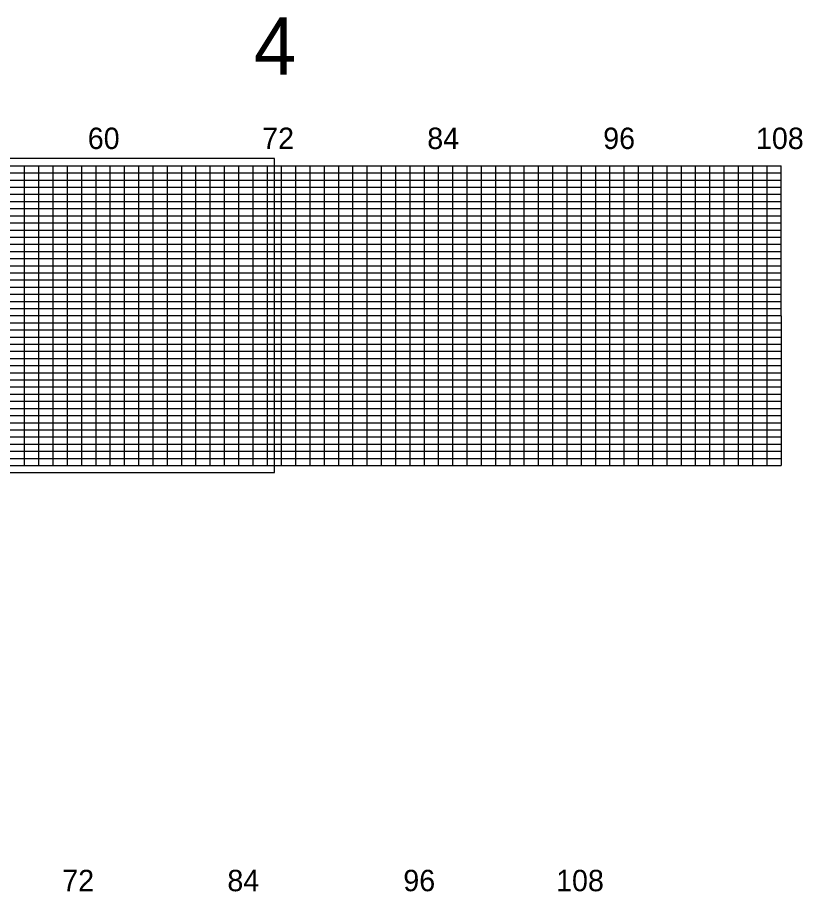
# Model space of a CAD drawing. Extents: x 1894907 to 1905782, y 740939 to 777025.
# Drawn here: x 1898307 to 1901056, y 769322 to 772384 of the extents above; entities that cross this region are included whole.
import ezdxf

# ---------------------------------------------------------------- set-up
doc = ezdxf.new("R2010")
doc.units = 0
for name, color, linetype in [('RD_PD_WallFill', 7, 'Continuous'), ('RD_SHT_IplotShp', 7, 'Continuous'), ('RD_Sketch8', 7, 'Continuous')]:
    doc.layers.add(name, color=color, linetype=linetype)

msp = doc.modelspace()

# ---------------------------------------------------------------- linework, layer by layer
at = {"layer": 'RD_PD_WallFill'}
for p, q in [((1895631.6, 771864.2), (1900981.6, 771864.2)), ((1898331.6, 770814.2), (1898331.6, 771864.2)), ((1898381.6, 770814.2), (1898381.6, 771864.2)), ((1898431.6, 770814.2), (1898431.6, 771864.2)), ((1898481.6, 770814.2), (1898481.6, 771864.2)), ((1898531.6, 770814.2), (1898531.6, 771864.2)), ((1898581.6, 770814.2), (1898581.6, 771864.2)), ((1898631.6, 770814.2), (1898631.6, 771864.2)), ((1898681.6, 770814.2), (1898681.6, 771864.2)), ((1898731.6, 770814.2), (1898731.6, 771864.2)), ((1898781.6, 770814.2), (1898781.6, 771864.2)), ((1898831.6, 770814.2), (1898831.6, 771864.2)), ((1898881.6, 770814.2), (1898881.6, 771864.2)), ((1898931.6, 770814.2), (1898931.6, 771864.2)), ((1898981.6, 770814.2), (1898981.6, 771864.2)), ((1899031.6, 770814.2), (1899031.6, 771864.2)), ((1899081.6, 770814.2), (1899081.6, 771864.2)), ((1899131.6, 770814.2), (1899131.6, 771864.2)), ((1899181.6, 770814.2), (1899181.6, 771864.2)), ((1899231.6, 770814.2), (1899231.6, 771864.2)), ((1899281.6, 770814.2), (1899281.6, 771864.2)), ((1899331.6, 770814.2), (1899331.6, 771864.2)), ((1899381.6, 770814.2), (1899381.6, 771864.2)), ((1899431.6, 770814.2), (1899431.6, 771864.2)), ((1899481.6, 770814.2), (1899481.6, 771864.2)), ((1899531.6, 770814.2), (1899531.6, 771864.2)), ((1899581.6, 770814.2), (1899581.6, 771864.2)), ((1899631.6, 770814.2), (1899631.6, 771864.2)), ((1899681.6, 770814.2), (1899681.6, 771864.2)), ((1899731.6, 770814.2), (1899731.6, 771864.2)), ((1899781.6, 770814.2), (1899781.6, 771864.2)), ((1899831.6, 770814.2), (1899831.6, 771864.2)), ((1899881.6, 770814.2), (1899881.6, 771864.2)), ((1899931.6, 770814.2), (1899931.6, 771864.2)), ((1899981.6, 770814.2), (1899981.6, 771864.2)), ((1900031.6, 770814.2), (1900031.6, 771864.2)), ((1900081.6, 770814.2), (1900081.6, 771864.2)), ((1900131.6, 770814.2), (1900131.6, 771864.2)), ((1900181.6, 770814.2), (1900181.6, 771864.2)), ((1900231.6, 770814.2), (1900231.6, 771864.2)), ((1900281.6, 770814.2), (1900281.6, 771864.2)), ((1900331.6, 770814.2), (1900331.6, 771864.2)), ((1900381.6, 770814.2), (1900381.6, 771864.2)), ((1900431.6, 770814.2), (1900431.6, 771864.2)), ((1900481.6, 770814.2), (1900481.6, 771864.2)), ((1900531.6, 770814.2), (1900531.6, 771864.2)), ((1900581.6, 770814.2), (1900581.6, 771864.2)), ((1900631.6, 770814.2), (1900631.6, 771864.2)), ((1900681.6, 770814.2), (1900681.6, 771864.2)), ((1900731.6, 770814.2), (1900731.6, 771864.2)), ((1900781.7, 770814.2), (1900781.6, 771864.2)), ((1900831.6, 770814.2), (1900831.7, 771864.2)), ((1900881.6, 770814.2), (1900881.6, 771864.2)), ((1900931.6, 770814.2), (1900931.6, 771864.2)), ((1900981.7, 770814.2), (1900981.6, 771864.2)), ((1896081.6, 771839.2), (1900981.6, 771839.2)), ((1896081.6, 771814.2), (1900981.6, 771814.2)), ((1896081.6, 771789.2), (1900981.6, 771789.2)), ((1896081.6, 771764.2), (1900981.6, 771764.2)), ((1895631.6, 771714.2), (1900981.6, 771714.2)), ((1896081.6, 771739.1), (1900981.6, 771739.2)), ((1895631.6, 771689.2), (1900981.6, 771689.1)), ((1895631.6, 771664.2), (1900981.6, 771664.2)), ((1895631.6, 771639.2), (1900981.6, 771639.1)), ((1895631.6, 771614.2), (1900981.6, 771614.2)), ((1895631.6, 771589.1), (1900981.6, 771589.2)), ((1895631.6, 771564.1), (1900981.6, 771564.2)), ((1895631.6, 771539.2), (1900981.6, 771539.1)), ((1895631.6, 771514.1), (1900981.6, 771514.2)), ((1895631.6, 771489.2), (1900981.6, 771489.2)), ((1895631.6, 771464.2), (1900981.6, 771464.1)), ((1895631.6, 771439.2), (1900981.6, 771439.2)), ((1895631.6, 771414.2), (1900981.6, 771414.1)), ((1895631.6, 771389.2), (1900981.6, 771389.2)), ((1895631.6, 771364.2), (1900981.6, 771364.2)), ((1895631.6, 771339.2), (1900981.6, 771339.1)), ((1895631.6, 771314.2), (1900981.6, 771314.2)), ((1895631.6, 771289.1), (1900981.6, 771289.2)), ((1895631.6, 771264.2), (1900981.6, 771264.2)), ((1895631.6, 771239.2), (1900981.6, 771239.2)), ((1895631.6, 771214.1), (1900981.6, 771214.2)), ((1895631.6, 771189.2), (1900981.6, 771189.1)), ((1895631.6, 771164.2), (1900981.6, 771164.2)), ((1895631.6, 771139.2), (1900981.6, 771139.2)), ((1895631.6, 771114.2), (1900981.6, 771114.1)), ((1895631.6, 771089.2), (1900981.6, 771089.2)), ((1895631.6, 771064.2), (1900981.6, 771064.2)), ((1895631.6, 771039.2), (1900981.6, 771039.2)), ((1895631.6, 771014.2), (1900981.6, 771014.2)), ((1895631.6, 770989.1), (1900981.6, 770989.2)), ((1895631.6, 770964.2), (1900981.6, 770964.1)), ((1895631.6, 770939.2), (1900981.6, 770939.2)), ((1895631.6, 770914.2), (1900981.6, 770914.2)), ((1895631.6, 770889.2), (1900981.6, 770889.2)), ((1895631.6, 770864.2), (1900981.6, 770864.2)), ((1895681.6, 770839.1), (1900981.6, 770839.2)), ((1895631.6, 770814.2), (1900981.6, 770814.1))]:
    msp.add_line(p, q, dxfattribs=at)
at = {"layer": 'RD_SHT_IplotShp'}
msp.add_lwpolyline([(1895606.6, 770789.2), (1899206.6, 770789.2), (1899206.6, 771889.1), (1895606.6, 771889.1)], close=True, dxfattribs=at)

# ---------------------------------------------------------------- texts
at = {"layer": 'RD_PD_WallFill'}
for s, p in [('60', (1898552.8, 771922.8)), ('72', (1899163.5, 771922.8)), ('84', (1899741.7, 771922.8)), ('96', (1900357.8, 771922.8)), ('108', (1900892.8, 771922.8)), ('72', (1898463.5, 769322.8)), ('84', (1899041.7, 769322.8)), ('96', (1899657.8, 769322.8)), ('108', (1900192.8, 769322.8))]:
    msp.add_text(s, height=75, dxfattribs=at).set_placement(p)
at = {"layer": 'RD_Sketch8'}
msp.add_text('4', height=200, dxfattribs=at).set_placement((1899134.4, 772183.6))

doc.saveas('drawing.dxf')
